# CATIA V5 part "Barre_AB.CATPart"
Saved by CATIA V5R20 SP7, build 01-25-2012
Part number: Barre_AB
Bounding box of the stored display mesh (mm): x 70 to 80, y 15 to 114.99, z -44 to 0
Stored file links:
  D:\IFMA\COURS\2A\projet balance IAO\catia\Barre_AB.CATPart
  D:\IFMA\COURS\2A\projet balance IAO\catia\Ass_projet_balance.CATProduct
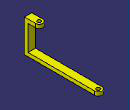
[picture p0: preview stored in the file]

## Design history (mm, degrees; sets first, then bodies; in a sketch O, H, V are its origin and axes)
Set1
  Plane1 "Plan.AB'": linked copy from another document
  Point1 "Point.B": linked copy from another document
  Point2 "Point.A": linked copy from another document
  Plane2 "Plan.KDAF": linked copy from another document
Body1 (main body)
  Sketch1 on Plane1, origin (0, 0, -44), H (1, 0, 0), V (0, 1, 0)
    arc A1 centre (75, 110) radius 5 from (80, 110) to (70, 110) ccw
    point P1 (75, 110)
    line L1 (80, 110) -> (80, 15)
    line L2 (70, 110) -> (70, 15)
    line L3 (80, 15) -> (70, 15)
    reference projected point E1 (75, 110) from Point1
    reference projected point E2 (75, 30) from Point2
    reference projected point E3 (75, 30) from Point2
    distance L1 L2 = 10
    distance L3 E2 = 15
    distance L1 E3 = 5
    tangency: L1 A1, L2 A1
    horizontal: L3 H
    coincidence: P1 E1
  Pad1: profile Sketch1, direction (0, 0, 1), length 5
  Sketch2 on Plane2, origin (0, 0, 0), H (1, 0, 0), V (0, 1, 0)
    arc A1 centre (75, 30) radius 5 from (80, 30) to (70, 30) ccw
    point P1 (75, 30)
    line L1 (70, 15) -> (80, 15)
    line L2 (80, 15) -> (80, 30)
    line L3 (70, 30) -> (70, 15)
    reference projected point E1 (75, 30) from Point2
    reference projected point E2 (75, 30) from Point2
    distance L2 L3 = 10
    distance L1 E2 = 15
    horizontal: L1 H
    vertical: L2 V, L3 V
    tangency: A1 L2, L3 A1
    coincidence: P1 E1
  Pad2: profile Sketch2, direction (0, 0, -1), length 5
  Sketch3 on end face of Pad1, origin (0, 0, -39), H (1, 0, 0), V (0, 1, 0)
    circle A1 centre (75, 110) radius 2.5
    point P1 (75, 110)
    reference projected point E1 (75, 110) from Point1
    radius A1 = 2.5
    coincidence: P1 E1
  Pocket1: profile Sketch3, direction (0, 0, -1), through (limit type 6)
  Sketch4 on start face of Pad2, origin (0, 0, 0), H (1, 0, 0), V (0, 1, 0)
    circle A1 centre (75, 30) radius 2.5
    point P1 (75, 30)
    reference projected point E1 (75, 30) from Point2
    radius A1 = 2.5
    coincidence: P1 E1
  Pocket2: profile Sketch4, direction (0, 0, -1), through (limit type 6)
  Sketch5 on face of Pad1 from Sketch1.L3, origin (0, 15, 0), H (1, 0, 0), V (0, 0, 1)
    line L1 (70, 0) -> (80, 0)
    line L2 (80, 0) -> (80, -44)
    line L3 (80, -44) -> (70, -44)
    line L4 (70, -44) -> (70, 0)
    reference projected point E1 (75, 0) from Point2
    reference projected point E2 (75, 0) from Point2
    reference intersected line E3 through (0, -44) direction (-1, 0) from Plane1
    distance L2 L4 = 10
    distance L2 E1 = 5
    distance L1 E2 = 0
    horizontal: L1 H, L3 H
    vertical: L2 V, L4 V
    coincidence: E3 L3
  Pad3: profile Sketch5, direction (0, 1, 0), length 5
